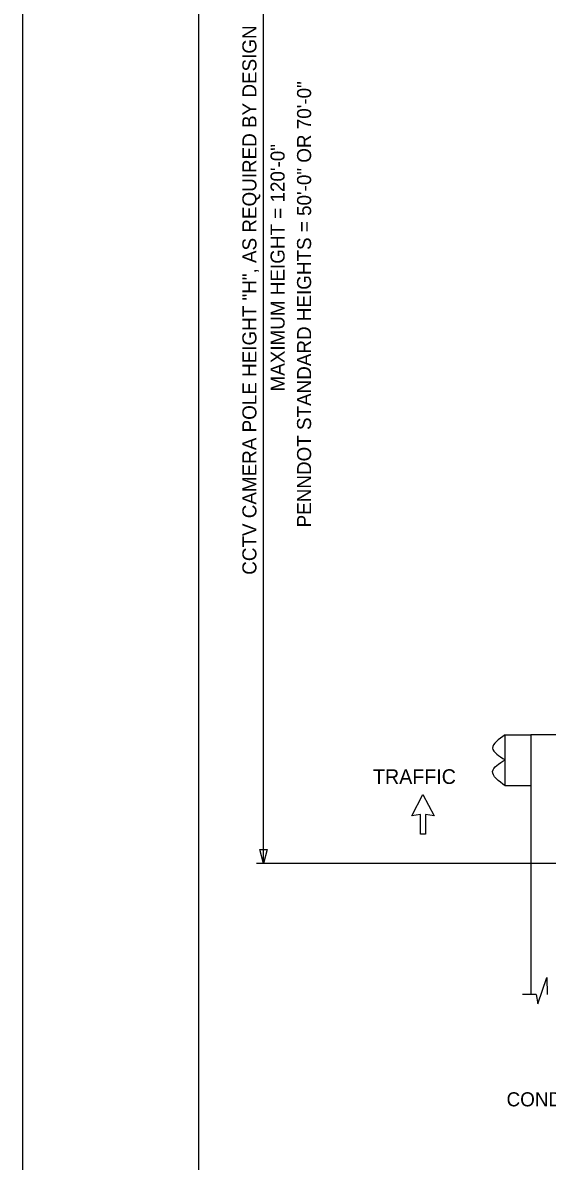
# Model space of a CAD drawing. Extents: x 1299104.7 to 1299141.5, y 239689.9 to 239711.9.
# Drawn here: x 1299104.72 to 1299109.19, y 239694.82 to 239704.52 of the extents above; entities that cross this region are included whole.
import ezdxf

# ---------------------------------------------------------------- set-up
doc = ezdxf.new("R2010")
doc.units = 0
for name, color, linetype in [('DIM TXT', 7, 'Continuous'), ('GS_plotshape_p', 7, 'Continuous'), ('Level 1', 7, 'Continuous'), ('Level 3', 7, 'Continuous'), ('Level 6', 7, 'Continuous'), ('Level 8', 7, 'Continuous')]:
    doc.layers.add(name, color=color, linetype=linetype)

msp = doc.modelspace()

# ---------------------------------------------------------------- linework, layer by layer
at = {"layer": 'GS_plotshape_p'}
msp.add_lwpolyline([(1299104.7224, 239711.8857), (1299138.7224, 239711.8857), (1299138.7224, 239689.8857), (1299104.7224, 239689.8857)], close=True, dxfattribs=at)
at = {"layer": 'Level 1'}
msp.add_lwpolyline([(1299138.2224, 239690.3857), (1299106.2224, 239690.3857), (1299106.2224, 239711.3857), (1299138.2224, 239711.3857)], close=True, dxfattribs=at)
at = {"layer": 'Level 3'}
for p, q in [((1299109.2861, 239698.4525), (1299109.0496, 239698.4525)), ((1299109.0496, 239698.4525), (1299109.0496, 239697.3558)), ((1299108.0347, 239697.7634), (1299108.1302, 239697.9457)), ((1299108.1302, 239697.9457), (1299108.2256, 239697.7634)), ((1299108.1085, 239697.7755), (1299108.0347, 239697.7634)), ((1299108.1085, 239697.6054), (1299108.1085, 239697.7755)), ((1299108.1518, 239697.7755), (1299108.1518, 239697.6054)), ((1299108.2256, 239697.7634), (1299108.1518, 239697.7755)), ((1299108.1518, 239697.6054), (1299108.1085, 239697.6054))]:
    msp.add_line(p, q, dxfattribs=at)
msp.add_lwpolyline([(1299109.0496, 239698.4525), (1299109.0496, 239698.0174), (1299108.8317, 239698.0174), (1299108.8317, 239698.4525)], close=True, dxfattribs=at)
for points in [[(1299108.8317, 239698.4525), (1299108.724, 239698.339), (1299108.8307, 239698.2401)], [(1299108.8317, 239698.0174), (1299108.724, 239698.1412), (1299108.8307, 239698.2401)]]:
    msp.add_spline(points, degree=3, dxfattribs=at)
at = {"layer": 'Level 6'}
msp.add_line((1299109.0496, 239697.3558), (1299109.0496, 239696.2398), dxfattribs=at)
at = {"layer": 'Level 8'}
for p, q in [((1299106.7727, 239697.3558), (1299106.7727, 239708.2308)), ((1299111.0738, 239697.3558), (1299106.7127, 239697.3558)), ((1299109.1085, 239696.1603), (1299109.187, 239696.3869)), ((1299109.187, 239696.3869), (1299109.1892, 239696.2401)), ((1299109.0961, 239696.2398), (1299108.9777, 239696.2398)), ((1299109.0961, 239696.2398), (1299109.1085, 239696.1603))]:
    msp.add_line(p, q, dxfattribs=at)
msp.add_lwpolyline([(1299106.8027, 239697.4758), (1299106.7727, 239697.3558), (1299106.7427, 239697.4758)], close=True, dxfattribs=at)

# ---------------------------------------------------------------- texts
at = {"layer": 'DIM TXT'}
for s, p in [('CCTV CAMERA POLE HEIGHT "H", AS REQUIRED BY DESIGN', (1299106.7127, 239699.8159)), ('PENNDOT STANDARD HEIGHTS = 50\'-0" OR 70\'-0"', (1299107.1783, 239700.2194)), ('MAXIMUM HEIGHT = 120\'-0"', (1299106.9527, 239701.3769))]:
    msp.add_text(s, height=0.12, rotation=90, dxfattribs=at).set_placement(p)
for s, height, p in [('TRAFFIC', 0.125, (1299107.7057, 239698.0343)), ('CONDUIT', 0.12, (1299108.843, 239695.2884))]:
    msp.add_text(s, height=height, dxfattribs=at).set_placement(p)

doc.saveas('drawing.dxf')
